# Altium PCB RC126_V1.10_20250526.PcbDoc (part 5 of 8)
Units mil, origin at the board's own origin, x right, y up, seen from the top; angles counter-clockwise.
Board outline 6299.62 x 3544.12 mil, 4 copper layers (Top, GND, Power, Bottom), stack 35.4 mil thick; 509 components, 417 nets, 1867 pads, 2150 vias.
Unrouted connection lines stored in the file: 1451.
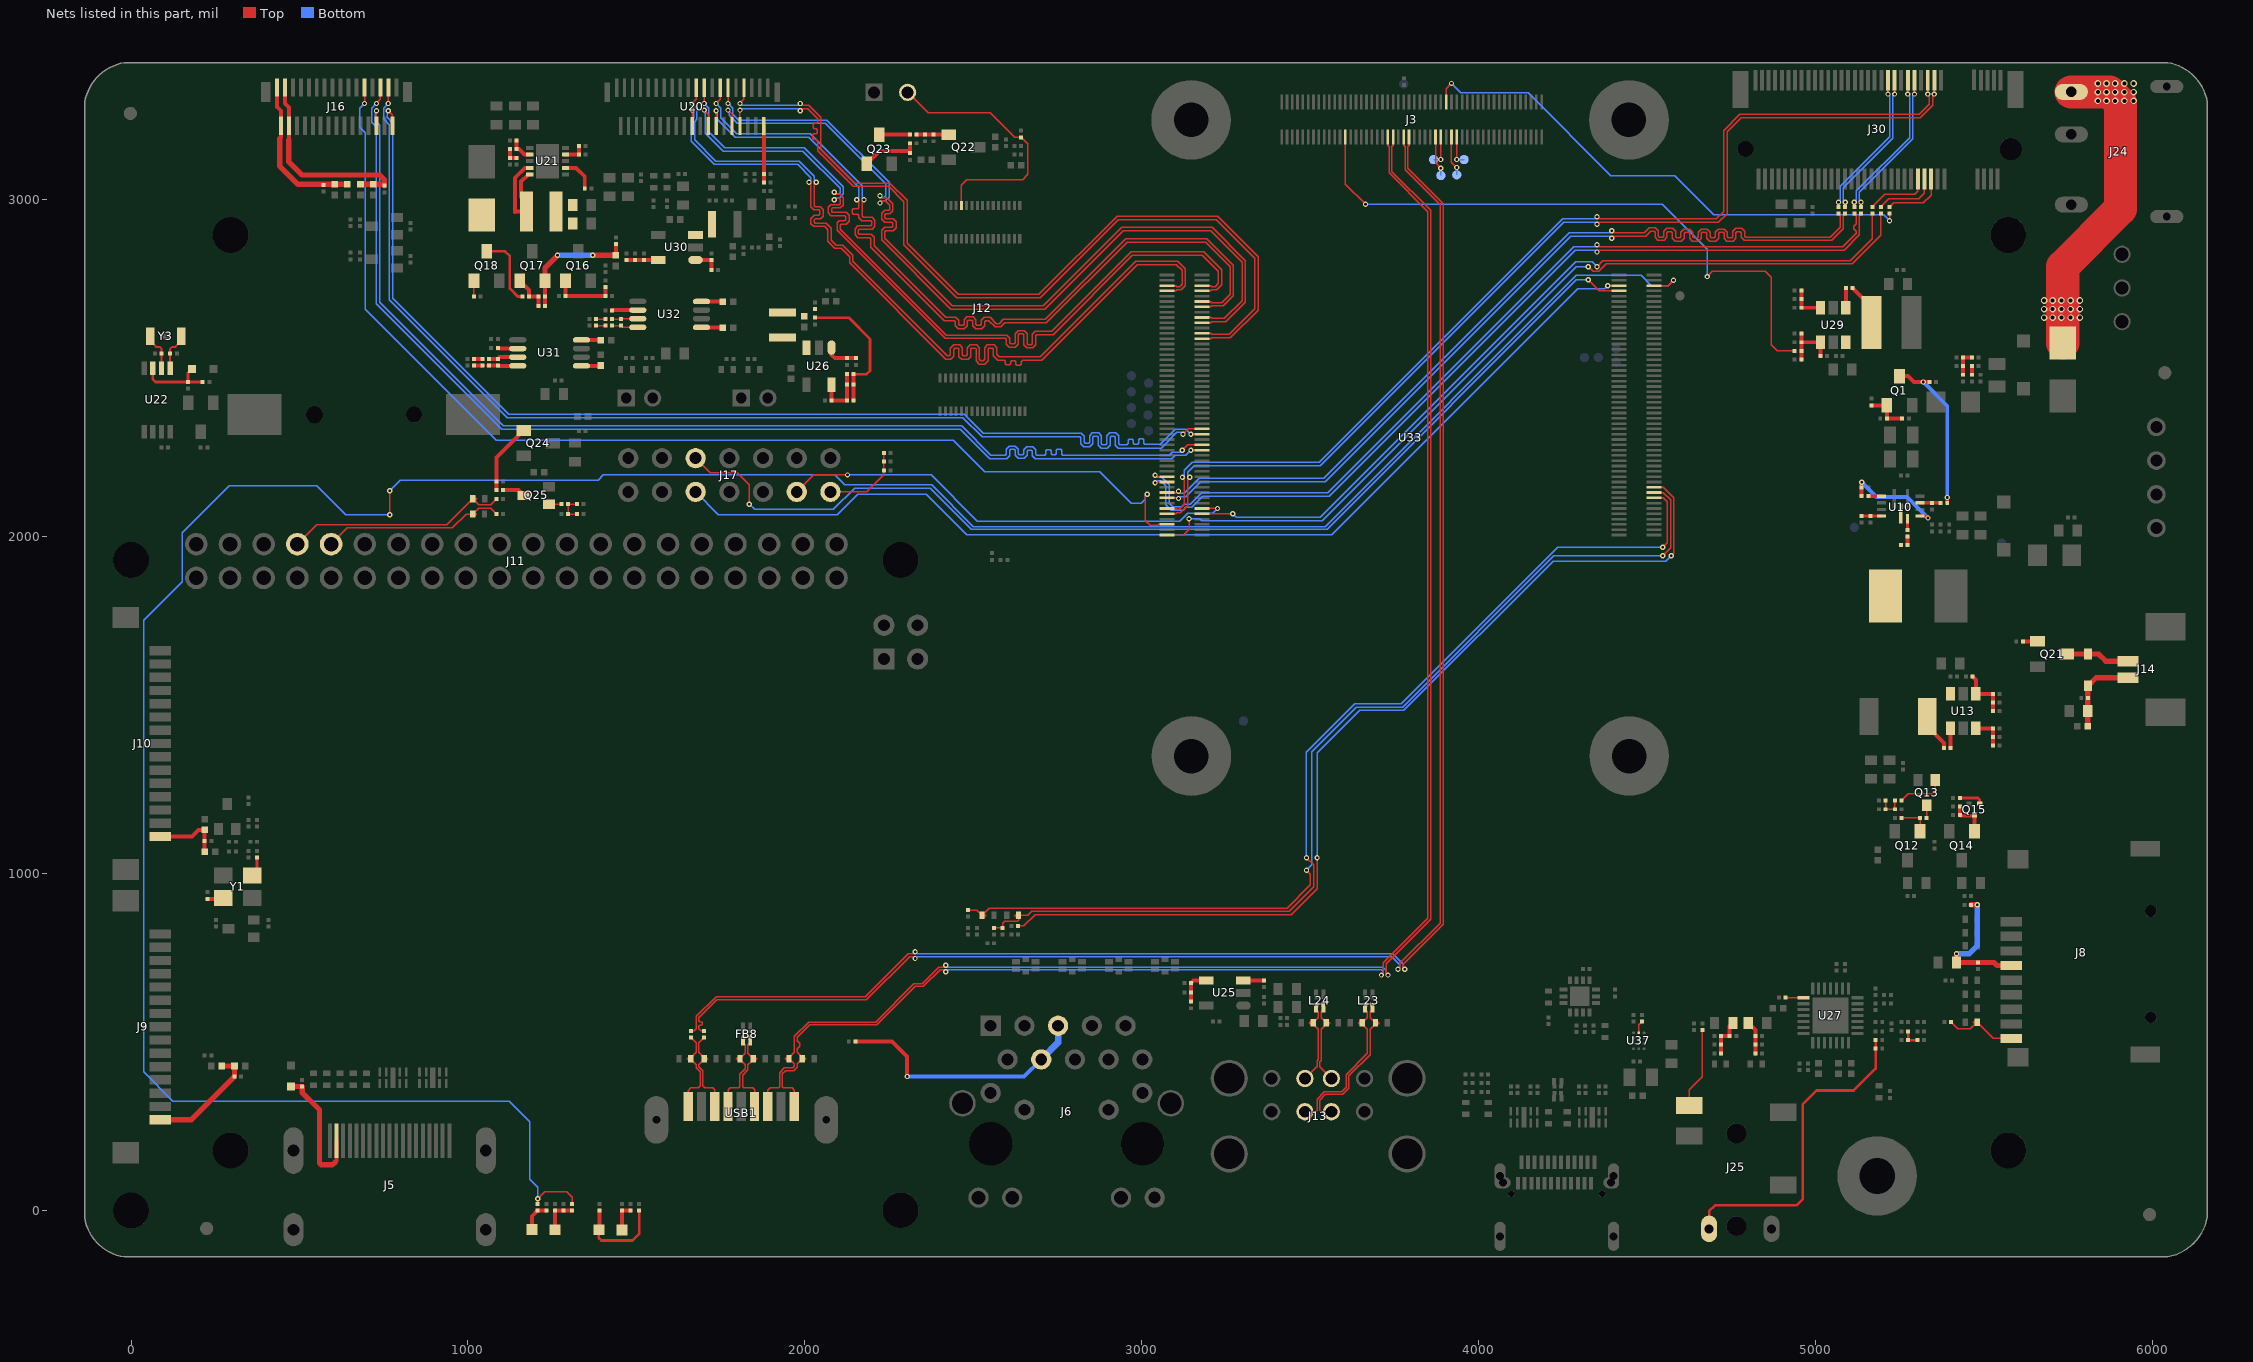
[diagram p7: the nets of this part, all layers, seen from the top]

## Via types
v1: diameter 15.75, hole 7.87, Top to Bottom, 2047 vias
v2: diameter 19.68, hole 11.81, Top to Bottom, 103 vias

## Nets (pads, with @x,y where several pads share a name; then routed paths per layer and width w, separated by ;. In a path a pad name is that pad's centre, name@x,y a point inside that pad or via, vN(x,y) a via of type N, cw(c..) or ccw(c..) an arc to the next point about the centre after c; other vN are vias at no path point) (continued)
MIPI_DPHY_CSI4_RX_CLKP: J16.9 U33.106 | length 3399.8
  Top w3.94: v1(692.91,3285.43) 692.91,3299.49 J16.9@692.91,3332.68 ; v1(3015.75,2125.98) 3009.84,2120.08 3009.84,2100.39 3009.84,2047.31 3023.89,2033.27 3046.26,2033.27 3049.21,2036.22 U33.106@3074.8,2036.22
  Bottom w3.94: v1(692.91,3285.43) 679.13,3271.65 679.13,3214.43 694.88,3198.68 694.88,2675.2 1083.66,2286.42 2439.96,2286.42 2533.46,2192.91 2874.02,2192.91 2968.5,2098.43 2998.03,2098.43 3009.84,2110.24 3009.84,2120.08 v1(3015.75,2125.98)
MIPI_DPHY_CSI4_RX_D0N: J16.5 U33.133 | length 3383.8
  Top w3.94: v1(728.35,3285.43) 740.16,3297.25 J16.5@740.16,3332.68 ; v1(3145.28,2256.69) U33.133@3178.74,2256.69
  Bottom w3.94: v1(728.35,3285.43) 714.57,3271.65 714.57,3230.32 728.35,3216.54 728.35,2690.81 1100.25,2318.9 1383.86,2318.9 2460.49,2318.9 2547.63,2231.76 2599.09,2231.76 2607.81,2240.47 2607.81,2255.91 2610.76,2258.86 2620.61,2258.86 2623.56,2255.91 2623.56,2241.99 2632.28,2233.27 2650.27,2233.27 2658.99,2241.99 2658.99,2253.94 2661.94,2256.89 2671.79,2256.89 2674.74,2253.94 2674.74,2240.02 2683.46,2231.3 3088.58,2231.3 3098.23,2240.94 3129.53,2240.94 v1(3145.28,2256.69)
MIPI_DPHY_CSI4_RX_D0P: J16.6 U33.135 | length 3386.7
  Top w3.94: J16.6@728.35,3219.5 728.35,3251.96 v1(728.35,3263.78) ; v1(3119.68,2256.69) 3135.43,2272.44 U33.135@3178.74,2272.44
  Bottom w3.94: v1(728.35,3263.78) 724.41,3259.84 724.41,3234.39 738.19,3220.61 738.19,2694.88 1104.33,2328.74 2330.51,2328.74 2464.57,2328.74 2551.71,2241.6 2595.02,2241.6 2597.97,2244.55 2597.97,2259.98 2606.69,2268.7 2624.68,2268.7 2633.4,2259.98 2633.4,2246.06 2636.35,2243.11 2646.2,2243.11 2649.15,2246.06 2649.15,2258.01 2657.87,2266.73 2675.86,2266.73 2684.58,2258.01 2684.58,2244.09 2686.78,2241.9 2711.39,2241.9 2714.57,2245.08 2714.57,2255.23 2717.52,2258.18 2727.36,2258.18 2730.32,2255.23 2730.32,2245.86 2733.27,2242.9 2743.11,2242.9 2746.06,2245.86 2746.06,2255.61 2749.02,2258.57 2758.86,2258.57 2761.81,2255.61 2761.81,2244.19 2764.86,2241.14 3080.71,2241.14 3090.35,2250.79 3113.78,2250.79 v1(3119.68,2256.69)
MIPI_DPHY_CSI4_RX_D1N: J16.2 U33.139 | length 3392.1
  Top w3.94: v1(763.78,3263.78) 775.59,3251.97 J16.2@775.59,3219.5 ; v1(3145.28,2303.94) U33.139@3178.74,2303.94
  Bottom w3.94: v1(763.78,3263.78) 759.84,3259.84 759.84,3244.23 776.57,3226.52 776.57,2706.83 1120.22,2363.19 2472.65,2363.19 2529.74,2306.1 2820.02,2306.1 2828.74,2297.38 2828.74,2279.53 2831.69,2276.57 2841.54,2276.57 2844.49,2279.53 2844.49,2299.35 2853.21,2308.07 2871.2,2308.07 2879.92,2299.35 2879.92,2275.59 2882.87,2272.64 2892.72,2272.64 2895.67,2275.59 2895.67,2299.35 2904.39,2308.07 2922.38,2308.07 2931.1,2299.35 2931.1,2275.59 2934.06,2272.64 2954.93,2272.64 2958.66,2276.37 2958.66,2285.98 2961.61,2288.94 2971.46,2288.94 2974.41,2285.98 2974.41,2276.37 2977.36,2273.42 2987.2,2273.42 2990.16,2276.37 2990.16,2287.51 2993.11,2290.47 3002.95,2290.47 3005.91,2287.51 3005.91,2276.57 3008.86,2273.62 3053.99,2273.62 3099.27,2318.9 3130.32,2318.9 v1(3145.28,2303.94)
MIPI_DPHY_CSI4_RX_D1P: J16.3 U33.141 | length 3383.6
  Top w3.94: v1(763.78,3285.43) 763.78,3299.49 J16.3@763.78,3332.68 ; v1(3121.65,2303.94) 3137.4,2319.69 U33.141@3178.74,2319.69
  Bottom w3.94: v1(763.78,3285.43) 750,3271.65 750,3240.16 766.73,3222.44 766.73,2702.76 1116.14,2353.35 2468.57,2353.35 2525.66,2296.26 2815.94,2296.26 2818.9,2293.31 2818.9,2275.45 2827.62,2266.73 2845.61,2266.73 2854.33,2275.45 2854.33,2295.28 2857.28,2298.23 2867.13,2298.23 2870.08,2295.28 2870.08,2271.51 2878.8,2262.8 2896.79,2262.8 2905.51,2271.51 2905.51,2295.28 2908.46,2298.23 2918.31,2298.23 2921.26,2295.28 2921.26,2271.51 2929.98,2262.8 3057.09,2262.8 3103.35,2309.06 3116.54,2309.06 v1(3121.65,2303.94)
MIPI_DPHY_DSI_TX_CLKN: U20.13 U33.187 | length 2466.5
  Top w3.94: v1(1736.22,3285.43) 1748.03,3297.24 U20.13@1748.03,3331.89 ; v1(2175.2,3000) 2169.29,2994.09 2169.29,2950.79 2172.24,2947.83 2198.96,2947.83 2207.68,2939.12 2207.68,2921.12 2198.96,2912.4 2161.42,2912.4 2158.46,2909.45 2158.46,2899.61 2161.42,2896.65 2196.99,2896.65 2205.71,2887.94 2205.71,2863.33 2417.99,2651.05 2447.52,2651.05 2456.24,2642.33 2456.24,2629.92 2459.19,2626.97 2469.03,2626.97 2471.98,2629.92 2471.98,2643.84 2480.7,2652.56 2498.7,2652.56 2507.42,2643.84 2507.42,2629.92 2510.37,2626.97 2520.21,2626.97 2523.17,2629.92 2523.17,2641.87 2531.88,2650.59 2549.88,2650.59 2568.35,2632.12 2576.54,2632.12 2589.11,2644.68 2712.6,2644.68 2951.77,2883.86 3192.91,2883.86 3271.65,2805.12 3271.65,2715.48 3241.01,2684.84 3207.68,2684.84 3204.72,2681.89 U33.187@3178.74,2681.89
  Bottom w3.94: v1(1736.22,3285.43) 1750,3271.65 1750,3242.27 1797.38,3194.88 2015.89,3194.88 2169.29,3041.48 2169.29,3005.91 v1(2175.2,3000)
MIPI_DPHY_DSI_TX_CLKP: U20.14 U33.189 | length 2450.3
  Top w3.94: U20.14@1736.22,3218.71 v1(1736.22,3263.78) ; v1(2153.54,3000) 2159.45,2994.09 2159.45,2975.39 2156.5,2972.44 2142.89,2972.44 2139.94,2969.49 2139.94,2959.65 2142.89,2956.69 2156.28,2956.69 2159.45,2953.52 2159.45,2946.71 2168.17,2937.99 2194.88,2937.99 2197.83,2935.04 2197.83,2925.2 2194.88,2922.24 2157.34,2922.24 2148.62,2913.53 2148.62,2895.53 2157.34,2886.81 2192.91,2886.81 2195.87,2883.86 2195.87,2859.25 2413.91,2641.21 2443.44,2641.21 2446.39,2638.25 2446.39,2625.84 2455.11,2617.13 2473.11,2617.13 2481.83,2625.84 2481.83,2639.76 2484.78,2642.72 2494.62,2642.72 2497.57,2639.76 2497.57,2625.84 2506.29,2617.13 2524.29,2617.13 2533.01,2625.84 2533.01,2637.8 2535.96,2640.75 2545.8,2640.75 2564.5,2622.05 2580.39,2622.05 2593.19,2634.84 2716.68,2634.84 2955.85,2874.02 3188.84,2874.02 3261.81,2801.04 3261.81,2719.56 3236.94,2694.68 3207.68,2694.68 3204.72,2697.64 U33.189@3178.74,2697.64
  Bottom w3.94: v1(1736.22,3263.78) 1740.16,3259.84 1740.16,3238.19 1793.31,3185.04 2011.81,3185.04 2159.45,3037.4 2159.45,3005.91 v1(2153.54,3000)
MIPI_DPHY_DSI_TX_D0N: U20.7 U33.175 | length 2464
  Top w3.94: v1(1807.09,3285.43) 1818.9,3297.24 U20.7@1818.9,3331.89 ; v1(1986.22,3285.43) 1992.13,3279.53 2011.81,3279.53 2047.24,3244.09 2047.24,3149.75 2147.78,3049.21 2252.11,3049.21 2303.15,2998.17 2303.15,2870.22 2454.86,2718.5 2693.9,2718.5 2926.18,2950.79 3224.41,2950.79 3344.49,2830.71 3344.49,2672.17 3262.67,2590.35 3207.68,2590.35 3204.72,2587.4 U33.175@3178.74,2587.4
  Bottom w3.94: v1(1807.09,3285.43) 1812.99,3279.53 1980.31,3279.53 v1(1986.22,3285.43)
MIPI_DPHY_DSI_TX_D0P: U20.8 U33.177 | length 2463.4
  Top w3.94: U20.8@1807.09,3218.71 v1(1807.09,3265.75) ; v1(1986.22,3263.78) 1992.13,3269.69 2007.73,3269.69 2037.4,3240.02 2037.4,3229.33 2034.45,3226.38 2027.25,3226.38 2024.3,3223.43 2024.3,3213.58 2027.25,3210.63 2033.37,3210.63 2036.32,3207.68 2036.32,3197.83 2033.37,3194.88 2026.16,3194.88 2023.2,3191.93 2023.2,3182.09 2026.16,3179.13 2031.92,3179.13 2037.4,3173.65 2037.4,3145.67 2143.7,3039.37 2248.03,3039.37 2293.31,2994.09 2293.31,2866.14 2450.79,2708.66 2697.97,2708.66 2930.26,2940.94 3220.33,2940.94 3334.65,2826.63 3334.65,2676.25 3258.59,2600.2 3207.68,2600.2 3204.72,2603.15 U33.177@3178.74,2603.15
  Bottom w3.94: v1(1807.09,3265.75) 1811.02,3269.69 1980.31,3269.69 v1(1986.22,3263.78)
MIPI_DPHY_DSI_TX_D1N: U20.10 U33.181 | length 2463.9
  Top w3.94: v1(1771.65,3265.75) 1783.46,3253.94 U20.10@1783.46,3218.71 ; v1(2222.44,3011.81) 2228.35,3005.91 2242.13,3005.91 2260.83,2987.2 2260.83,2967.38 2252.11,2958.66 2240.16,2958.66 2237.2,2955.71 2237.2,2945.87 2240.16,2942.91 2261.95,2942.91 2270.67,2934.2 2270.67,2916.2 2261.95,2907.48 2240.16,2907.48 2237.2,2904.53 2237.2,2884.98 2437.15,2685.04 2707.54,2685.04 2939.82,2917.32 3208.66,2917.32 3307.09,2818.9 3307.09,2695.8 3248.89,2637.6 3207.68,2637.6 3204.72,2634.65 U33.181@3178.74,2634.65
  Bottom w3.94: v1(1771.65,3265.75) 1770.74,3264.83 1775.59,3259.98 1775.59,3250 1799.21,3226.38 2060.88,3226.38 2240.16,3047.1 2240.16,3011.81 2234.25,3005.91 2228.35,3005.91 v1(2222.44,3011.81)
MIPI_DPHY_DSI_TX_D1P: U20.11 U33.183 | length 2465.1
  Top w3.94: v1(1771.65,3285.43) U20.11@1771.65,3331.89 ; v1(2222.44,2990.16) 2228.35,2996.06 2238.05,2996.06 2250.98,2983.13 2250.98,2971.46 2248.03,2968.5 2236.08,2968.5 2227.36,2959.79 2227.36,2941.79 2236.08,2933.07 2257.87,2933.07 2260.83,2930.12 2260.83,2920.28 2257.87,2917.32 2236.08,2917.32 2227.36,2908.6 2227.36,2904.53 2227.36,2880.91 2433.07,2675.2 2711.61,2675.2 2943.9,2907.48 3204.58,2907.48 3297.24,2814.82 3297.24,2699.87 3244.81,2647.44 3207.68,2647.44 3204.72,2650.39 U33.183@3178.74,2650.39
  Bottom w3.94: v1(1771.65,3285.43) 1785.43,3271.65 1785.43,3254.08 1803.29,3236.22 2064.96,3236.22 2250,3051.18 2250,3007.73 2238.33,2996.06 2228.35,2996.06 v1(2222.44,2990.16)
MIPI_DPHY_DSI_TX_D2N: U20.16 U33.193 | length 2455.7
  Top w3.94: v1(1700.79,3265.75) 1712.6,3253.94 U20.16@1712.6,3218.71 ; v1(2086.61,3021.65) 2087.6,3022.64 2094.49,3015.75 2104.33,3015.75 2114.17,3005.91 2114.17,2984.04 2105.4,2975.27 2081.57,2975.27 2078.74,2972.44 2078.74,2964.57 2080.71,2962.6 2122.19,2962.6 2130.91,2953.88 2130.91,2935.88 2122.19,2927.17 2108.27,2927.17 2105.31,2924.21 2105.31,2912.54 2419.96,2597.9 2599.09,2597.9 2607.81,2589.18 2607.81,2574.8 2610.76,2571.85 2620.61,2571.85 2623.56,2574.8 2623.56,2602.5 2632.28,2611.22 2650.27,2611.22 2658.99,2602.5 2658.99,2572.83 2661.94,2569.88 2671.79,2569.88 2674.74,2572.83 2674.74,2600.53 2683.46,2609.25 2732.21,2609.25 2967.84,2844.88 3182.68,2844.88 3236.22,2791.34 3236.22,2747.05 3221.26,2732.09 3207.68,2732.09 3204.72,2729.13 U33.193@3178.74,2729.13
  Bottom w3.94: v1(1700.79,3265.75) 1699.87,3264.83 1704.72,3259.98 1704.72,3196.85 1757.87,3143.7 1994.09,3143.7 2104.33,3033.46 2104.33,3021.17 2098.91,3015.75 2092.52,3015.75 v1(2086.61,3021.65)
MIPI_DPHY_DSI_TX_D2P: U20.17 U33.195 | length 2458.1
  Top w3.94: v1(1700.79,3285.43) U20.17@1700.79,3331.89 ; v1(2086.61,3000) 2092.52,3005.91 2100.25,3005.91 2104.33,3001.83 2104.33,2988.12 2101.45,2985.24 2077.13,2985.24 2068.9,2977 2068.9,2960.49 2076.63,2952.76 2118.11,2952.76 2121.06,2949.8 2121.06,2939.96 2118.11,2937.01 2101.38,2937.01 2095.47,2931.1 2095.47,2908.46 2415.88,2588.06 2595.02,2588.06 2597.97,2585.1 2597.97,2570.73 2606.69,2562.01 2624.68,2562.01 2633.4,2570.73 2633.4,2598.43 2636.35,2601.38 2646.2,2601.38 2649.15,2598.43 2649.15,2568.76 2657.87,2560.04 2675.86,2560.04 2684.58,2568.76 2684.58,2596.46 2687.53,2599.41 2736.29,2599.41 2971.91,2835.03 3178.61,2835.03 3226.38,2787.26 3226.38,2751.12 3217.18,2741.93 3207.68,2741.93 3204.72,2744.88 U33.195@3178.74,2744.88
  Bottom w3.94: v1(1700.79,3285.43) 1714.57,3271.65 1714.57,3200.93 1761.95,3153.54 1998.17,3153.54 2114.17,3037.54 2114.17,3017.09 2102.99,3005.91 2092.52,3005.91 v1(2086.61,3000)
MIPI_DPHY_DSI_TX_D3N: U20.19 U33.194 | length 2468.2
  Top w3.94: v1(1665.35,3285.43) 1677.17,3297.24 U20.19@1677.17,3331.89 ; v1(2033.46,3051.18) 2027.56,3045.28 2027.56,2982.28 2030.51,2979.33 2045.42,2979.33 2054.13,2970.61 2054.13,2950.79 2047.24,2943.9 2031.74,2943.9 2027.56,2939.71 2027.56,2933.07 2030.51,2930.12 2063.06,2930.12 2077.76,2915.42 2077.76,2879.99 2092.59,2865.16 2112.27,2865.16 2142.16,2835.27 2142.16,2816.57 2422.31,2536.42 2428.15,2536.42 2431.1,2539.37 2431.1,2559.19 2440.81,2568.9 2458.8,2568.9 2466.54,2561.16 2466.54,2539.37 2469.49,2536.42 2479.33,2536.42 2482.28,2539.37 2482.28,2561.16 2490.02,2568.9 2509.98,2568.9 2517.72,2561.16 2517.72,2525.59 2521.65,2521.65 2529.53,2521.65 2533.46,2525.59 2533.46,2561.16 2541.2,2568.9 2561.16,2568.9 2568.9,2561.16 2568.9,2541.34 2576.77,2533.46 2697.83,2533.46 2981.3,2816.93 3106.37,2816.93 3128.94,2794.36 3128.94,2744.09 3116.93,2732.09 3103.35,2732.09 3100.39,2729.13 U33.194@3074.8,2729.13
  Bottom w3.94: v1(1665.35,3285.43) 1679.13,3271.65 1679.13,3238.19 1672.24,3231.3 1672.24,3177.31 1735.38,3114.17 1982.28,3114.17 2027.56,3068.9 2027.56,3057.09 v1(2033.46,3051.18)
MIPI_DPHY_DSI_TX_D3P: U20.20 U33.196 | length 2466.7
  Top w3.94: U20.20@1665.35,3218.71 v1(1665.35,3265.75) ; v1(2011.81,3051.18) 2017.72,3045.28 2017.72,2978.21 2026.43,2969.49 2041.34,2969.49 2044.29,2966.54 2044.29,2956.69 2041.34,2953.74 2027.56,2953.74 2017.72,2943.9 2017.72,2928.99 2026.44,2920.28 2058.99,2920.28 2067.91,2911.35 2067.91,2875.91 2088.51,2855.32 2108.2,2855.32 2132.32,2831.2 2132.32,2812.49 2418.23,2526.58 2432.23,2526.58 2440.94,2535.3 2440.94,2555.12 2444.88,2559.06 2454.72,2559.06 2456.69,2557.09 2456.69,2533.46 2464.57,2525.59 2484.25,2525.59 2492.13,2533.46 2492.13,2557.09 2494.09,2559.06 2505.91,2559.06 2507.87,2557.09 2507.87,2521.51 2517.58,2511.81 2533.6,2511.81 2543.31,2521.51 2543.31,2557.09 2545.28,2559.06 2557.09,2559.06 2559.06,2557.09 2559.06,2537.26 2572.69,2523.62 2591.54,2523.62 2594.49,2520.67 2594.49,2513.03 2597.44,2510.07 2607.28,2510.07 2610.24,2513.03 2610.24,2519.59 2613.19,2522.55 2623.03,2522.55 2625.98,2519.59 2625.98,2511.12 2628.94,2508.17 2638.78,2508.17 2641.73,2511.12 2641.73,2518.9 2646.45,2523.62 2701.91,2523.62 2985.38,2807.09 3102.29,2807.09 3119.09,2790.28 3119.09,2748.17 3112.85,2741.93 3103.35,2741.93 3100.39,2744.88 U33.196@3074.8,2744.88
  Bottom w3.94: v1(1665.35,3265.75) 1669.29,3261.81 1669.29,3242.27 1662.4,3235.38 1662.4,3173.23 1731.3,3104.33 1978.21,3104.33 2017.72,3064.82 2017.72,3057.09 v1(2011.81,3051.18)
N16483578: C284.2 R334.1 | length 25.6
  Top w11.81: C284.2@1017.72,2527.56 R334.1@1043.31,2527.56
N16483700: C289.2 R335.1 | length 25.6
  Top w11.81: C289.2@1017.72,2507.87 R335.1@1043.31,2507.87
N16485789: C291.2 R336.1 | length 27.6
  Top w3.94: C291.2@1379.92,2645.67 R336.1@1407.48,2645.67
N16485911: C296.2 R337.1 | length 27.6
  Top w3.94: C296.2@1379.92,2625.98 R337.1@1407.48,2625.98
N17781029: LED2.1 R219.2 R221.2 | length 88.8
  Top w11.81: LED2.1@1189.82,-56.24 1189.82,-16.87 R221.2@1206.69,0 R219.2@1232.28,0
N17781033: LED3.1 R224.2 R227.1 | length 281.9
  Top w8: LED3.1@1388.64,-57.43 1387.8,-58.27 1387.8,-80.71 1395.67,-88.58 1488.19,-88.58 1507.87,-68.9 R227.1@1507.87,0
  Top w11.81: LED3.1@1388.64,-57.43 1389.76,-56.3 R224.2@1389.76,0
N17781361: LED2.2 R216.1 R217.1 R222.1 | length 107.7
  Top w11.81: LED2.2@1258.21,-56.35 1258.21,-0.34 R216.1@1257.87,0 R217.1@1283.46,0 R222.1@1309.06,0
N17782008: LED3.2 R225.1 R226.1 | length 83.3
  Top w11.81: LED3.2@1457.03,-57.54 1456.69,-57.2 R225.1@1456.69,0 R226.1@1482.28,0
N17782924: J17.13 R218.1 R220.1 R223.1 | length 244.5
  Top w3.94: J17.13@2075.59,2132.68 2183.86,2132.68 2234.25,2183.07 R218.1@2234.25,2196.85 R223.1@2234.25,2222.44 R220.1@2234.25,2248.03
N17878168: C278.2 C279.1 FB17.1 R317.1 | length 99.5
  Top w11.81: C278.2@4799.21,557.09 4820.87,535.43 R317.1@4820.87,517.72 C279.1@4820.87,492.13 FB17.1@4820.87,466.54
N17943889: R268.2 Y1.3 | length 66.9
  Top w7.87: Y1.3@360.24,994.09 374.02,994.09 R268.2@374.02,1047.24
N17943950: R264.1 Y1.1 | length 48.1
  Top w11.81: R264.1@226.38,925.2 257.87,925.2 259.85,927.17 Y1.1@273.62,927.17
N18372552: C192.1 C193.1 FB1.1 J9.1 | length 342.4
  Top w15.75: J9.1@86.61,269.7 179.14,269.7 C193.1@307.09,397.64 C192.1@307.09,429.13 FB1.1@269.69,429.13
N18373067: C190.1 C191.1 FB3.1 J10.1 | length 205
  Top w11.81: J10.1@86.61,1110.25 181.11,1110.25 200.79,1129.92 C190.1@218.5,1129.92 C191.1@218.5,1096.46 FB3.1@218.5,1064.96
N18669719: C277.1 R291.2 R304.1 | length 53.1
  Top w7.87: R291.2@5273.62,531.5 R304.1@5273.62,505.91 C277.1@5301.18,505.91
N19430296: D18.2 J8.9 R228.2 | length 214.5
  Top w3.94: R228.2@5401.57,559.06 5421.26,539.37 5458.66,539.37 D18.2@5478.35,559.06 5526.77,510.63 J8.9@5579.7,510.63
N19463865: J30.52 R296.1 | length 188.3
  Top w3.94: R296.1@5192.91,2978.35 5216.54,3001.97 5305.12,3001.97 5322.05,3018.9 J30.52@5322.05,3061.22
N19463875: C222.2 J30.49 | length 446
  Top w3.94: C222.2@5133.86,2978.35 v1(5133.86,2992.13) ; v1(5292.52,3313.19) J30.49@5292.52,3354.53
  Bottom w3.94: v1(5133.86,2992.13) 5128.94,2997.05 5128.94,3021.58 5287.6,3180.25 5287.6,3308.27 v1(5292.52,3313.19)
N19463877: C221.2 J30.47 | length 446
  Top w3.94: C221.2@5114.17,2978.35 v1(5114.17,2992.13) ; v1(5272.84,3313.19) J30.47@5272.83,3354.53
  Bottom w3.94: v1(5114.17,2992.13) 5119.09,2997.05 5119.09,3025.66 5277.76,3184.32 5277.76,3308.27 v1(5272.84,3313.19)
N19463923: J30.50 R295.1 | length 190.7
  Top w3.94: R295.1@5167.32,2978.35 5204.72,3015.75 5293.31,3015.75 5302.36,3024.8 J30.50@5302.36,3061.22
N19463941: C210.1 U29.1 | length 59.1
  Top w11.81: U29.1@5088.58,2679.13 C210.1@5088.58,2738.19
N19463943: C210.2 L21.1 U29.6 | length 126
  Top w11.81: C210.2@5108.27,2738.19 5165.35,2681.11 L21.1@5165.35,2635.83
N19463949: J30.54 R297.1 | length 185.8
  Top w3.94: R297.1@5218.5,2978.35 5230.32,2990.16 5318.9,2990.16 5341.73,3012.99 J30.54@5341.73,3061.22
N19463955: C217.2 R285.2 R290.1 U29.3 | length 108.3
  Top w11.81: R285.2@4956.69,2730.32 C217.2@4956.69,2704.72 R290.1@4956.69,2679.13 U29.3@5013.78,2679.13
N19463973: C220.1 R7.2 R278.1 R288.2 R298.2 U29.4 | length 178.1
  Top w11.81: R288.2@4956.69,2525.59 R7.2@4956.69,2551.18 R298.2@4956.69,2574.8 ; C220.1@4956.69,2602.36 R298.2@4956.69,2574.8 ; R278.1@5013.78,2535.43 U29.4@5013.78,2576.77 5013.78,2576.09 5013.1,2576.77 R298.2@4956.69,2576.77 R298.2@4956.69,2574.8
N19471161: J30.41 R293.2 | length 441.1
  Top w3.94: R293.2@5066.93,2978.35 v1(5066.93,2992.13) ; v1(5213.78,3313.19) J30.41@5213.78,3354.53
  Bottom w3.94: v1(5066.93,2992.13) 5071.85,2997.05 5071.85,3039.44 5218.7,3186.29 5218.7,3308.27 v1(5213.78,3313.19)
N19471204: J30.43 R294.2 | length 441.1
  Top w3.94: R294.2@5086.61,2978.35 v1(5086.61,2992.13) ; v1(5233.46,3313.19) J30.43@5233.46,3354.53
  Bottom w3.94: v1(5086.61,2992.13) 5081.69,2997.05 5081.69,3035.36 5228.54,3182.21 5228.54,3308.27 v1(5233.46,3313.19)
N19591793: C181.1 Q17.2 R254.2 R255.2 R257.1 | length 371.8
  Top w11.81: R257.1@1228.35,2685.04 C181.1@1228.35,2712.6 Q17.2@1228.34,2759.84 ; R254.2@1438.98,2834.65 R255.2@1438.98,2868.11
  Top w15.75: Q17.2@1228.34,2759.84 1228.34,2797.24 v1(1265.75,2834.65) ; v1(1370.08,2834.65) R254.2@1438.98,2834.65
  Bottom w15.75: v1(1265.75,2834.65) v1(1370.08,2834.65)
N19591801: C181.2 Q17.1 R257.2 R261.1 | length 113.8
  Top w11.81: Q17.1@1153.54,2759.84 1181.1,2732.28 R261.1@1181.1,2712.6 C181.2@1208.66,2712.6 R257.2@1208.66,2685.04
N19591813: Q18.3 R261.2 | length 218.3
  Top w7.87: Q18.3@1055.12,2846.46 1110.24,2846.46 1124.02,2832.68 1124.02,2736.22 1147.64,2712.6 R261.2@1161.42,2712.6
N19591825: Q18.1 R262.2 | length 47.2
  Top w3.94: R262.2@1017.72,2712.6 Q18.1@1017.72,2759.84
N19591849: C174.1 C176.1 FB2.2 L20.1 U21.7 | length 103.1
  Top w11.81: U21.7@1289.37,3094.49 1320.87,3094.49 1346.46,3068.9 C174.1@1346.46,3033.46
N19591855: D24.1 L20.2 U21.4 U21.5 | length 322.5
  Top w11.81: U21.5@1183.46,3074.8 1179.13,3074.8 1157.48,3053.15 1157.48,3007.87 1173.11,2992.25 L20.2@1173.11,2964.57 1141.73,2964.57 1139.76,2962.6 1139.76,3064.96 1169.29,3094.49 U21.4@1183.46,3094.49
N19591857: R240.1 R249.2 U21.2 | length 71.9
  Top w11.81: R240.1@1143.7,3175.2 R249.2@1143.7,3149.61 1151.57,3149.61 1167.32,3133.86 U21.2@1183.46,3133.86
N19591859: C180.2 R247.2 R249.1 | length 45.3
  Top w11.81: R249.1@1124.02,3149.61 R247.2@1124.02,3124.02 C180.2@1143.7,3124.02
N19591867: R236.2 R246.2 U21.9 | length 65
  Top w11.81: U21.9@1289.37,3133.86 R236.2@1328.74,3133.86 R246.2@1328.74,3159.45
N19592734: R229.2 R233.2 U20.2 | length 167.5
  Top w11.81: R233.2@1877.95,3051.18 R229.2@1877.95,3076.77 U20.2@1877.95,3218.71
N19592784: Q16.1 R234.2 R235.1 R243.2 | length 189
  Top w11.81: Q16.1@1289.37,2759.84 R243.2@1289.37,2714.57 R234.2@1407.48,2714.57 R235.1@1407.48,2740.16
N23443315: C275.2 C280.1 FB16.1 R286.2 R316.1 | length 120.2
  Top w11.81: FB16.1@4718.5,466.54 R316.1@4718.5,492.13 R286.2@4718.5,517.72 C280.1@4744.09,517.72 4744.09,547.24 C275.2@4753.94,557.09
N31344489: FB23.1 U31.8 | length 57.5
  Top w11.81: U31.8@1336.61,2583.67 1392.71,2583.67 FB23.1@1393.7,2582.68
N31344544: C283.2 U31.2 | length 59.5
  Top w11.81: C283.2@1088.58,2559.06 1089.56,2558.07 U31.2@1147.64,2558.07
N31344597: C286.1 R334.2 U31.3 | length 86.7
  Top w11.81: R334.2@1062.99,2527.56 C286.1@1088.58,2527.56 1093.5,2532.48 U31.3@1147.64,2532.48
N31344662: C286.2 R335.2 U31.4 | length 92.9
  Top w11.81: R335.2@1062.99,2507.87 1059.06,2507.87 C286.2@1088.58,2507.87 1089.57,2506.89 U31.4@1147.64,2506.89
N31344668: FB24.1 U31.5 | length 57.5
  Top w11.81: U31.5@1336.61,2506.89 1392.71,2506.89 FB24.1@1393.7,2507.87
N31367008: C293.1 R336.2 U32.3 | length 77.2
  Top w3.94: R336.2@1427.17,2645.67 C293.1@1454.72,2645.67 1455.71,2646.65 U32.3@1503.94,2646.65
N31367020: C293.2 R337.2 U32.4 | length 78.8
  Top w3.94: R337.2@1427.17,2625.98 C293.2@1454.72,2625.98 1459.65,2621.06 U32.4@1503.94,2621.06
N31367085: FB25.1 U32.8 | length 63.4
  Top w11.81: U32.8@1692.91,2697.84 1754.92,2697.84 FB25.1@1755.91,2696.85
N31367111: C290.2 U32.2 | length 77.2
  Top w11.81: C290.2@1427.17,2671.26 1428.15,2672.25 U32.2@1503.94,2672.25
N31367151: FB26.1 U32.5 | length 63.4
  Top w11.81: U32.5@1692.91,2621.06 1754.93,2621.06 FB26.1@1755.91,2620.08
N34109734: C167.1 C168.1 J8.4 R31.2 | length 402.3
  Top w15.75: v1(5417.32,761.81) C167.1@5417.32,736.22 C168.1@5480.32,736.22 5528.35,736.22 5537.4,727.17 J8.4@5579.7,727.17 ; R31.2@5460.63,907.48 v1(5478.35,907.48)
  Bottom w15.75: v1(5417.32,761.81) 5454.72,761.81 5478.35,785.43 v1(5478.35,907.48)
N37314098: L22.1 U26.3
N37314100: C201.1 C203.1 C206.1 L22.2 R284.1 R287.1 R289.1 | length 416
  Top w7.87: C206.1@2029.53,2649.61 2129.92,2649.61 2192.91,2586.61 2192.91,2492.13 2183.07,2482.28 R289.1@2143.7,2482.28
  Top w11.81: R287.1@2143.7,2403.54 C201.1@2143.7,2450.79 R289.1@2143.7,2482.28
N37314140: C201.2 R287.2 R289.2 R318.1 U26.5 | length 171.3
  Top w11.81: U26.5@2078.74,2450.79 R318.1@2078.74,2403.54 R287.2@2124.02,2403.54 C201.2@2124.02,2450.79 R289.2@2124.02,2482.28
N37314178: L29.1 U30.3
N37314204: R331.2 R332.1 U30.1 | length 76.8
  Top w11.81: U30.1@1675.2,2820.87 R332.1@1722.44,2820.87 R331.2@1722.44,2791.34
N37314206: C242.2 R329.2 R330.1 U30.5 | length 96.5
  Top w3.94: R330.1@1519.68,2820.87 R330.1@1521.65,2820.87
  Top w11.81: R329.2@1470.47,2820.87 C242.2@1496.06,2820.87 1519.68,2820.87 U30.5@1564.96,2820.87
N37314307: C228.2 Q22.1 R321.2 R322.1 | length 96.5
  Top w11.81: R322.1@2330.71,3192.91 C228.2@2356.3,3192.91 R321.2@2381.89,3192.91 2396.65,3192.91 Q22.1@2427.16,3192.91
N37314321: Q23.3 R322.2 | length 90.6
  Top w11.81: Q23.3@2220.47,3192.92 2270.67,3192.92 R322.2@2311.02,3192.91
N37314323: C232.1 Q23.1 R323.2 | length 178.9
  Top w11.81: Q23.1@2183.07,3106.3 2220.48,3143.7 2311.02,3143.7 C232.1@2311.02,3137.8 R323.2@2311.02,3167.32
N38149696: C175.1 D8.2 J5.18 | length 399.4
  Top w11.81: 604.33,142.05 609.92,147.64 J5.18@609.92,207.82
  Top w15.75: D8.2@474.41,368.11 C175.1@507.87,368.11 507.87,350.39 559.06,299.21 559.06,141.73 564.96,135.83 598.11,135.83 604.33,142.05
N38162604: C150.1 R181.2 U10.6 | length 59.1
  Top w9.84: R181.2@5135.83,2061.02 C150.1@5161.42,2061.02 U10.6@5194.88,2061.02
N38162840: C163.1 R185.2 R202.1 R204.2 U13.4 | length 157.6
  Top w11.81: R185.2@5464.57,1584.65 5474.41,1574.8 U13.4@5474.41,1533.46 C163.1@5525.59,1533.46 R202.1@5525.59,1507.87 R204.2@5525.59,1482.28
N38162882: C152.2 L15.1 U13.6 | length 114.9
  Top w11.81: L15.1@5330.71,1466.54 5336.61,1460.63 5336.61,1431.1 5379.92,1387.8 C152.2@5379.92,1372.05
N38162884: C152.1 U13.1 | length 59.1
  Top w11.81: C152.1@5399.61,1372.05 U13.1@5399.61,1431.1
N38162900: C160.2 R187.2 R205.1 U13.3 | length 102.4
  Top w11.81: U13.3@5474.41,1431.1 R205.1@5525.59,1431.1 R187.2@5525.59,1405.51 C160.2@5525.59,1379.92
N38162991: D4.1 J24.1 | length 942.6
  Top w98.43: D4.1@5732.28,2574.8 5732.28,2801.18 5903.54,2972.44 5903.54,3287.4 5871.26,3319.69 J24.1@5757.87,3319.69
  other v2: 5677.17,2649.61 5702.76,2649.61 5728.35,2649.61 5755.91,2649.61 5783.46,2649.61 5677.17,2675.2 5702.76,2675.2 5728.35,2675.2 5755.91,2675.2 5783.46,2675.2 5677.17,2700.79 5702.76,2700.79 5728.35,2700.79 5755.91,2700.79 5783.46,2700.79 5836.61,3293.31 5862.2,3293.31 5887.8,3293.31 5915.35,3293.31 5942.91,3293.31 5836.61,3318.9 5862.2,3318.9 5887.8,3318.9 5915.35,3318.9 5942.91,3318.9 5836.61,3344.49 5862.2,3344.49 5887.8,3344.49 5915.35,3344.49 5942.91,3344.49
N38163032: C155.2 R201.2 | length 25.6
  Top w11.81: C155.2@5462.6,2480.31 R201.2@5462.6,2505.91
N38163042: C148.1 R176.1 R178.2 R179.2 | length 76.8
  Top w11.81: R176.1@5437.01,2480.31 C148.1@5437.01,2505.91 R179.2@5437.01,2531.5 R178.2@5462.6,2531.5
N38163178: C151.1 R182.2 U10.9 | length 308.3
  Top w7.87: U10.9@5309.06,2061.02 5326.77,2061.02 v1(5332.68,2055.12)
  Top w11.81: R182.2@5135.83,2120.08 C151.1@5135.83,2145.67 v1(5135.83,2161.42)
  Bottom w11.81: v1(5135.83,2161.42) 5179.13,2118.11 5269.68,2118.11 v1(5332.68,2055.12)
N38163182: C77.2 L2.1 U10.7
N38163194: R115.1 U10.8 | length 33.5
  Top w9.84: R115.1@5271.65,2019.69 U10.8@5271.66,2053.15
N38163196: C77.1 R115.2 | length 25.6
  Top w11.81: C77.1@5271.65,1974.41 R115.2@5271.65,2000
N38163206: R175.1 R177.2 U10.11 | length 63
  Top w3.94: R177.2@5344.49,2100.39 R177.2@5346.45,2100.39
  Top w9.84: U10.11@5309.06,2100.39 5346.46,2100.39 R175.1@5370.08,2100.39
N38163220: R182.1 U10.3 | length 39.4
  Top w9.84: R182.1@5155.51,2120.08 U10.3@5194.88,2120.08
N38163995: Q12.1 R206.1 R208.1 | length 94.5
  Top w3.94: R206.1@5253.94,1165.35 R208.1@5309.06,1165.35 Q12.1@5309.05,1125.99
N38164007: R209.2 R210.1 R326.2 R327.2 | length 78.7
  Top w3.94: R326.2@5206.69,1216.54 R327.2@5206.69,1190.94 R210.1@5234.25,1190.94 R209.2@5234.25,1216.54
N38164009: Q13.1 R209.1 | length 144.1
  Top w3.94: R209.1@5253.94,1216.54 5273.62,1236.22 5344.49,1236.22 5354.33,1246.06 Q13.1@5354.33,1277.56
N38164029: Q13.3 R208.2 | length 37.4
  Top w3.94: R208.2@5328.74,1165.35 Q13.3@5328.74,1202.76
N38175041: C173.2 Q14.1 Q15.3 R213.1 | length 115.2
  Top w11.81: C173.2@5427.17,1198.82 R213.1@5427.17,1173.23 5428.74,1171.65 Q15.3@5470.37,1171.65 5470.47,1171.56 Q14.1@5470.47,1125.99
N38175045: Q15.1 R230.2 | length 71.3
  Top w7.87: R230.2@5427.17,1224.41 5480.32,1224.41 5486.22,1218.5 Q15.1@5486.22,1208.66
N38179051: C187.2 U22.1 Y3.1 | length 114.1
  Top w5.91: U22.1@116.14,2500 C187.2@116.14,2543.31 116.14,2557.09 122.05,2562.99 131.89,2562.99 147.64,2578.74 147.64,2592.52 Y3.1@149.61,2594.49
N38179153: C189.2 U22.2 Y3.2 | length 114.1
  Top w5.91: Y3.2@57.09,2594.49 59.06,2592.52 59.06,2578.74 74.8,2562.99 84.65,2562.99 90.55,2557.09 C189.2@90.55,2543.31 U22.2@90.55,2500
N38179175: D30.2 R16.2 R265.2 U22.3 | length 228.6
  Top w7.87: U22.3@64.96,2500 64.96,2466.54 72.83,2458.66 R16.2@169.29,2458.66 ; D30.2@181.1,2498.03 169.29,2486.22 R16.2@169.29,2458.66 ; R265.2@212.6,2458.66 R16.2@169.29,2458.66
N38183775: D3.1 J11.8 R273.1 | length 661.7
  Top w3.94: J11.8@493.7,1977.56 551.57,2035.43 937.01,2035.43 D3.1@1014.17,2112.6 1032.28,2094.49 1066.93,2094.49 R273.1@1084.65,2112.2
N38194639: D2.1 J11.10 R274.1 | length 542.6
  Top w3.94: J11.10@593.7,1977.56 641.73,2025.59 952.76,2025.59 994.09,2066.93 D2.1@1013.78,2066.93 1031.5,2084.65 1066.93,2084.65 R274.1@1084.65,2066.93
N38198421: D35.2 FB8.3 R283.1 USB1.3 | length 258.1
  Top w3.94: R283.1@1836.61,513.78 1836.61,499.01 FB8.3@1837.6,499.01 1830.71,492.12 1830.71,466.54 D35.2@1846.46,450.79 1839.97,441.35 1830.71,432.09 1830.71,417.32 1814.96,401.57 1814.96,367.13 1817.91,364.17 1844.49,364.17 1850.39,358.27 USB1.3@1850.39,308.66
N38198427: C204.2 D39.2 USB1.8 | length 256.7
  Top w3.94: C204.2@1700.79,513.78 1685.04,498.03 1685.04,494.09 1685.04,469.49 1694.31,460.22 D39.2@1700.79,450.79 1694.31,441.35 1685.04,432.09 1685.04,426.49 1696.85,414.68 1696.85,370.08 1702.76,364.17 1726.38,364.17 1732.28,358.27 USB1.8@1732.28,308.66
N38198429: C205.2 D37.2 USB1.9 | length 255.6
  Top w3.94: USB1.9@1653.54,308.66 1653.54,356.3 1661.42,364.17 1683.07,364.17 1688.98,370.08 1688.98,411.42 1677.17,423.23 1677.17,432.09 1667.9,441.35 D37.2@1661.42,450.79 1667.9,460.22 1677.17,469.49 1677.17,494.09 1677.17,498.03 C205.2@1661.42,513.78
N38198493: D38.2 FB8.4 R282.1 USB1.2 | length 257.5
  Top w3.94: USB1.2@1771.65,308.66 1771.65,358.27 1777.56,364.17 1804.13,364.17 1807.09,367.13 1807.09,404.84 1822.83,420.58 1822.83,432.09 1813.57,441.35 D38.2@1807.09,450.79 1822.83,466.54 1822.83,492.12 FB8.4@1815.94,499.01 1816.93,500 R282.1@1816.93,513.78
N38202668: R277.2 R279.1 R280.1 U25.4 | length 103.7
  Top w11.81: R277.2@3145.67,620.08 R280.1@3145.67,647.64 R279.1@3145.67,675.2 3153.54,683.07 U25.4@3190.95,683.07
N38213216: R354.1 U37.D2 | length 37.5
  Top w3.94: U37.D2@4474.41,527.56 4474.41,551.18 R354.1@4484.25,561.02
N38228022: C197.1 C200.1 D6.2 FB9.2 J14.2 | length 251.3
  Top w3.94: C197.1@5807.09,1519.69 C197.1@5807.09,1521.65
  Top w15.75: FB9.2@5807.09,1437.01 C200.1@5807.09,1482.28 5807.09,1519.69 D6.2@5807.09,1557.09 5831.1,1581.1 J14.2@5926.38,1581.1
N38228074: D6.1 J14.1 Q21.3 | length 191.1
  Top w15.75: Q21.3@5744.1,1651.57 D6.1@5807.09,1651.57 5838.98,1651.57 5860.24,1630.32 J14.1@5926.38,1630.32
N38228088: Q21.1 R14.2 | length 43.3
  Top w11.81: R14.2@5614.17,1688.98 Q21.1@5657.48,1688.97
N38240450: C231.1 C233.1 FB4.1 J16.28 J16.29 | length 624.2
  Top w3.94: C233.1@718.5,3045.28 C233.1@719.36,3045.28
  Top w11.02: 468.5,3177.17 J16.28@468.5,3219.5
  Top w11.81: J16.29@456.69,3332.68 456.69,3285.43 468.5,3273.62 J16.28@468.5,3219.5
  Top w15.75: 468.5,3177.17 468.5,3112.2 507.87,3072.83 738.19,3072.83 751.97,3059.06 C231.1@751.97,3041.34 751.97,3045.28 719.36,3045.28 FB4.1@681.1,3045.28
N38240452: C234.1 C235.1 FB5.1 J16.30 J16.31 | length 465.3
  Top w3.94: C235.1@569.42,3045.28 570.87,3043.83 C235.1@570.87,3043.31 ; C234.1@604.02,3045.28 C234.1@604.33,3045.28
  Top w11.02: 440.94,3181.1 444.88,3185.04 J16.30@444.88,3219.5
  Top w11.81: J16.31@433.07,3332.68 433.07,3275.59 444.88,3263.78 J16.30@444.88,3219.5
  Top w15.75: 440.94,3181.1 440.94,3100.39 496.06,3045.28 569.42,3045.28 604.02,3045.28 FB5.1@641.73,3045.28
N38245392: Q24.1 R344.1 R350.1 | length 210.6
  Top w11.81: R350.1@1084.65,2137.8 R344.1@1084.65,2163.39 1084.65,2234.25 Q24.1@1165.35,2314.96
N38245412: R356.2 R357.2 R358.2 R359.1 | length 80.7
  Top w3.94: R356.2@1322.83,2066.93 R359.1@1297.24,2066.93 R358.2@1297.24,2096.46 R357.2@1322.83,2096.46
N38245414: Q25.1 R358.1 | length 37.4
  Top w3.94: Q25.1@1240.16,2096.46 R358.1@1277.56,2096.46
N38245434: Q25.3 R350.2 | length 67.5
  Top w11.81: R350.2@1104.33,2137.8 1149.61,2137.8 Q25.3@1165.36,2122.05
N38274077: Q1.3 R1.2 R175.2 | length 483.5
  Top w11.81: Q1.3@5248.03,2476.38 5273.62,2476.38 5291.34,2458.66 v1(5318.9,2458.66) R1.2@5336.61,2458.66 ; R175.2@5389.76,2100.39 v1(5389.76,2116.14)
  Bottom w11.81: v1(5318.9,2458.66) 5389.76,2387.8 v1(5389.76,2116.14)
N38274095: Q1.1 R2.2 R5.1 R6.2 | length 134
  Top w11.81: R2.2@5165.35,2389.76 5207.76,2389.76 5210.63,2386.89 Q1.1@5210.63,2389.76 R6.2@5210.63,2350.39 R5.1@5255.91,2350.39
N38368976: J2.2 J12.46 R15.2 | length 781.6
  Top w3.94: J2.2@2304.72,3318.5 2365.35,3257.87 2549.21,3257.87 2622.05,3185.04 R15.2@2641.73,3185.04 2661.42,3165.35 2661.42,3074.8 2645.67,3059.06 2480.51,3059.06 2464.17,3042.72 J12.46@2464.17,2982.28
N38434760: D41.2 J13.2 L23.4 R299.2 | length 461
  Top w3.94: J13.2@3483.46,293.31 3515.75,293.31 3519.68,297.24 3519.68,330.71 3541.34,352.36 3592.52,352.36 3606.3,366.14 3606.3,403.21 3669.29,466.2 3669.29,538.39 3660.03,547.65 D41.2@3653.54,557.09 3669.29,572.83 3669.29,590.54 L23.4@3662.4,597.44 3663.39,597.44 R299.2@3663.39,612.2
N38434788: D42.2 J13.3 L23.3 R301.2 | length 458.8
  Top w3.94: J13.3@3562.2,293.31 3531.5,293.31 3527.56,297.24 3527.56,327.45 3544.6,344.49 3595.78,344.49 3614.17,362.88 3614.17,399.94 3677.17,462.94 3677.17,538.39 3686.43,547.65 D42.2@3692.91,557.09 3677.17,572.83 3677.17,590.54 L23.3@3684.06,597.44 3683.07,598.42 R301.2@3683.07,612.2
N38448541: R281.1 U25.3 | length 61
  Top w11.81: U25.3@3301.18,683.07 R281.1@3362.2,683.07
N38452344: D44.2 J13.6 L24.4 R300.2 | length 252.7
  Top w3.94: J13.6@3483.46,391.73 3519.68,427.95 3519.68,444.54 3523.62,448.48 3523.62,538.39 3514.36,547.65 D44.2@3507.87,557.09 3523.62,572.83 3523.62,590.54 L24.4@3516.73,597.44 3517.72,598.42 R300.2@3517.72,612.2
N38452372: D43.2 J13.7 L24.3 R302.2 | length 252.1
  Top w3.94: R302.2@3537.4,612.2 3537.4,598.42 L24.3@3538.39,597.44 3531.5,590.54 3531.5,572.83 D43.2@3547.24,557.09 3540.76,547.65 3531.5,538.39 3531.5,445.22 3527.56,441.28 3527.56,426.38 J13.7@3562.2,391.73
N38457128: C169.2 J6.4 J6.5 | length 771.1
  Top w11.81: C169.2@2149.61,501.97 2257.87,501.97 2303.15,456.69 v1(2303.15,397.64)
  Bottom w11.81: v1(2303.15,397.64) 2650.39,397.64 J6.4@2701.18,448.43
  Bottom w19.68: J6.4@2701.18,448.43 2751.18,498.43 J6.5@2751.18,548.43
N38490894: J25.2 R26.2 R27.2 | length 971.3
  Top w7.87: J25.2@4683.07,-54.33 4683.07,-1.97 4700.79,15.75 4942.91,15.75 4960.63,33.46 4960.63,314.96 5001.97,356.3 5112.2,356.3 5177.17,421.26 R27.2@5177.17,480.32 R26.2@5177.17,505.91
N38492034: J25.4 R19.2 | length 239.9
  Top w3.94: J25.4@4624.02,311.81 4624.02,358.27 4663.39,397.64 R19.2@4663.39,535.43
N38837471: R276.2 U27.8 | length 53.1
  Top w3.94: R276.2@4909.45,631.89 U27.8@4962.6,631.89
N39005536: R303.2 R315.1 U26.1 | length 98.6
  Top w11.81: U26.1@2078.74,2561.02 2078.74,2539.37 2088.58,2529.53 R315.1@2124.02,2529.53 R303.2@2151.57,2529.53
NPWR_LED: R221.1 R222.2 U33.95 | length 8310.7
  Top w3.94: v1(767.72,2064.96) v1(767.72,2135.83) ; R221.1@1206.69,19.69 v1@1206.69,34.6 ; v1(1206.69,35.43) v1@1206.69,34.6 ; R222.2@1309.06,19.69 1309.06,39.37 1293.31,55.12 1227.22,55.12 v1@1206.69,34.6 ; U33.95@4520.08,2744.88 4561.42,2744.88 v1(4577.17,2760.63)
  Bottom w3.94: v1(767.72,2064.96) 637.8,2064.96 551.18,2151.57 291.34,2151.57 151.57,2011.81 151.57,1866.14 37.4,1751.97 37.4,411.42 124.02,324.8 1122.05,324.8 1183.07,263.78 1183.07,92.52 1206.69,68.9 v1(1206.69,35.43) ; v1(767.72,2135.83) 799.21,2167.32 1385.83,2167.32 1401.57,2183.07 2088.58,2183.07 2118.11,2153.54 2375.98,2153.54 2500,2029.53 3543.31,2029.53 4289.37,2775.59 4481.1,2775.59 4511.81,2744.88 4561.42,2744.88 v1(4577.17,2760.63)
PCIE0_CLKREQN_M0: R296.2 U33.102 | length 2586.1
  Top w3.94: U33.102@3074.8,2004.72 3122.83,2004.72 3139.76,2021.65 v1(3139.76,2053.15) ; v1(4324.8,2801.18) 4338.58,2787.4 4356.3,2787.4 4377.95,2809.06 5108.27,2809.06 5192.91,2893.7 R296.2@5192.91,2958.66
  Bottom w3.94: v1(3139.76,2053.15) 3171.8,2053.15 3177.71,2047.24 3535.43,2047.24 4289.37,2801.18 v1(4324.8,2801.18)
PCIE0_PERSTN: R295.2 U33.109 | length 2421.7
  Top w3.94: U33.109@3178.74,2067.72 v1(3269.29,2067.72) ; v1(4350.39,2801.18) 4368.11,2818.9 5102.36,2818.9 5167.32,2883.86 R295.2@5167.32,2958.66
  Bottom w3.94: v1(3269.29,2067.72) 3279.92,2057.09 3529.53,2057.09 4287.4,2814.96 4336.61,2814.96 v1(4350.39,2801.18)
PCIE0_PWREN_H: J3.76 R7.1 | length 1856.2
  Top w3.94: J3.76@3603.55,3185.83 3603.55,3177.1 3603.54,3046.06 v1(3663.39,2986.22) ; v1(4677.17,2771.65) 4692.91,2787.4 4850.39,2787.4 4868.11,2769.69 4868.11,2568.9 4885.83,2551.18 R7.1@4937.01,2551.18
  Bottom w3.94: v1(3663.39,2986.22) 4543.31,2986.22 4677.17,2852.36 v1(4677.17,2771.65)
PCIE0_SOC_REFCLKN: J30.53 U33.112 | length 3043.9
  Top w3.94: U33.112@3074.8,2083.46 3100.39,2083.46 3103.35,2080.51 3110.1,2080.51 3125.98,2096.4 3125.98,2170.08 v1(3120.08,2175.98) ; v1(4350.39,2948.82) 4356.3,2942.91 4704.65,2942.91 4726.38,2964.64 4726.38,3204.79 4774.54,3252.95 5306.23,3252.95 5336.81,3283.53 5336.81,3308.27 v1(5331.89,3313.19) J30.53@5331.89,3354.53
  Bottom w3.94: v1(3120.08,2175.98) 3125.98,2181.89 3125.98,2196.85 3149.61,2220.47 3525.59,2220.47 4248.03,2942.91 4344.49,2942.91 v1(4350.39,2948.82)
PCIE0_SOC_REFCLKP: J30.55 U33.110 | length 3060.7
  Top w3.94: U33.110@3074.8,2067.72 3100.39,2067.72 3103.35,2070.67 3114.17,2070.67 3135.83,2092.32 3135.83,2170.08 v1(3141.73,2175.98) ; v1(4350.39,2927.17) 4356.3,2933.07 4710.7,2933.07 4736.22,2958.59 4736.22,3200.72 4778.61,3243.11 5310.31,3243.11 5346.65,3279.46 5346.65,3308.27 v1(5351.58,3313.19) J30.55@5351.57,3354.53
  Bottom w3.94: v1(3141.73,2175.98) 3135.83,2181.89 3135.83,2191.73 3154.72,2210.63 3529.67,2210.63 4252.11,2933.07 4344.49,2933.07 v1(4350.39,2927.17)
PCIE0_SOC_RXN: R293.1 U33.118 | length 2601.9
  Top w3.94: U33.118@3074.8,2130.71 3104.33,2130.71 v1(3108.27,2134.65) ; v1(4393.7,2907.48) 4393.7,2903.54 4395.67,2901.57 4491,2901.57 4505.77,2916.34 4523.76,2916.34 4532.48,2907.62 4532.48,2891.73 4535.43,2888.78 4545.28,2888.78 4548.23,2891.73 4548.23,2905.65 4556.95,2914.37 4574.94,2914.37 4583.66,2905.65 4583.66,2889.76 4586.61,2886.81 4596.46,2886.81 4599.41,2889.76 4599.41,2903.68 4608.13,2912.4 4626.12,2912.4 4634.84,2903.68 4634.84,2889.76 4637.8,2886.81 4647.64,2886.81 4650.59,2889.76 4650.59,2903.68 4659.31,2912.4 4677.31,2912.4 4686.02,2903.68 4686.02,2889.76 4688.98,2886.81 4698.82,2886.81 4701.77,2889.76 4701.77,2903.68 4710.49,2912.4 4728.49,2912.4 4737.2,2903.68 4737.2,2889.76 4740.16,2886.81 4750,2886.81 4752.95,2889.76 4752.95,2905.65 4761.67,2914.37 4779.67,2914.37 4788.39,2905.65 4788.39,2891.73 4791.34,2888.78 5043.24,2888.78 5071.85,2917.39 5071.85,2953.74 R293.1@5066.93,2958.66
  Bottom w3.94: v1(3108.27,2134.65) 3114.17,2128.74 3125.84,2128.74 3170.33,2173.23 3183.99,2173.23 3539.37,2173.23 4267.72,2901.57 4387.8,2901.57 v1(4393.7,2907.48)
PCIE0_SOC_RXP: R294.1 U33.116 | length 2617.4
  Top w3.94: U33.116@3074.8,2114.96 3106.3,2114.96 v1(3108.27,2112.99) ; v1(4393.7,2885.83) 4393.7,2889.76 4395.67,2891.73 4495.08,2891.73 4509.84,2906.5 4519.69,2906.5 4522.64,2903.54 4522.64,2887.66 4531.36,2878.94 4549.35,2878.94 4558.07,2887.66 4558.07,2901.57 4561.02,2904.53 4570.87,2904.53 4573.82,2901.57 4573.82,2885.69 4582.54,2876.97 4600.53,2876.97 4609.25,2885.69 4609.25,2899.61 4612.2,2902.56 4622.05,2902.56 4625,2899.61 4625,2885.69 4633.72,2876.97 4651.71,2876.97 4660.43,2885.69 4660.43,2899.61 4663.39,2902.56 4673.23,2902.56 4676.18,2899.61 4676.18,2885.69 4684.9,2876.97 4702.9,2876.97 4711.61,2885.69 4711.61,2899.61 4714.57,2902.56 4724.41,2902.56 4727.36,2899.61 4727.36,2885.69 4736.08,2876.97 4754.08,2876.97 4762.8,2885.69 4762.8,2901.57 4765.75,2904.53 4775.59,2904.53 4778.54,2901.57 4778.54,2887.66 4787.26,2878.94 5047.31,2878.94 5081.69,2913.32 5081.69,2953.74 R294.1@5086.61,2958.66
  Bottom w3.94: v1(3108.27,2112.99) 3114.17,2118.9 3129.92,2118.9 3174.41,2163.39 3543.45,2163.39 4271.79,2891.73 4387.8,2891.73 v1(4393.7,2885.83)
PCIE0_SOC_TXN: C221.1 U33.124 | length 2596.5
  Top w3.94: v1(3038.98,2181.89) 3042.91,2177.95 U33.124@3074.8,2177.95 ; v1(4350.39,2866.14) 4356.3,2860.24 5079.65,2860.24 5119.09,2899.68 5119.09,2906.5 5112.2,2913.39 5112.2,2921.26 5119.09,2928.15 5119.09,2953.74 C221.1@5114.17,2958.66
  Bottom w3.94: v1(3038.98,2181.89) 3044.88,2175.98 3059.06,2175.98 3080.71,2154.33 3080.71,2098.56 3090.69,2088.58 3118.11,2088.58 3125.98,2096.46 3143.56,2096.46 3177.03,2129.92 3186.87,2129.92 3551.18,2129.92 4281.5,2860.24 4344.49,2860.24 v1(4350.39,2866.14)
PCIE0_SOC_TXP: C222.1 U33.122 | length 2606.3
  Top w3.94: v1(3038.98,2160.24) 3040.94,2162.2 U33.122@3074.8,2162.2 ; v1(4350.39,2844.49) 4356.3,2850.39 5083.73,2850.39 5128.94,2895.6 5128.94,2953.74 C222.1@5133.86,2958.66
  Bottom w3.94: v1(3038.98,2160.24) 3044.88,2166.14 3054.98,2166.14 3070.87,2150.25 3070.87,2094.49 3086.61,2078.74 3122.19,2078.74 3130.06,2086.61 3147.64,2086.61 3181.1,2120.08 3555.26,2120.08 4285.57,2850.39 4344.49,2850.39 v1(4350.39,2844.49)
PCIE0_WAKEN_M0: J3.37 R297.2 | length 1552.2
  Top w3.94: J3.37@3902.76,3289.77 3902.76,3298 3902.76,3329.13 v1(3918.5,3344.88) ; v1(5218.5,2937.01) R297.2@5218.5,2958.66
  Bottom w3.94: v1(3918.5,3344.88) 3946.46,3316.93 4145.67,3316.93 4391.73,3070.87 4580.71,3070.87 4696.85,2954.72 5200.79,2954.72 v1(5218.5,2937.01)
PCIE1_CLKREQN_M0: J3.34 P15.1 | length 88.6
  Top w3.94: v1(3934.25,3118.9) 3934.25,3180.7 J3.34@3934.26,3185.83
  Bottom w3.94: v1(3934.25,3118.9) P15.1@3955.91,3118.9
PCIE1_PERSTN: J3.36 P16.1 | length 118.7
  Top w3.94: J3.36@3918.51,3185.83 3918.51,3181.3 3918.5,3111.02 v1(3934.25,3095.28)
  Bottom w3.94: P16.1@3934.25,3073.62 v1(3934.25,3095.28)
PCIE1_REFCLKN: J3.42 P13.1 | length 120.7
  Top w3.94: J3.42@3871.26,3185.83 3871.26,3180.4 3871.26,3109.06 v1(3887.01,3093.31)
  Bottom w3.94: P13.1@3887.01,3071.65 v1(3887.01,3093.31)
PCIE1_REFCLKP: J3.40 P12.1 | length 88.6
  Top w3.94: v1(3887.01,3118.9) 3887.01,3176.7 J3.40@3887.01,3185.83
  Bottom w3.94: P12.1@3865.35,3118.9 v1(3887.01,3118.9)
PCIE1_RXN/USB3_OTG1_SSRXN: D40.2 J3.60 USB1.5 | length 4722.8
  Top w3.94: USB1.5@1968.5,308.66 1968.5,357.68 1962.01,364.17 1936.02,364.17 1933.07,367.13 1933.07,406.19 1942.24,415.35 1966.54,415.35 1976.38,425.2 1976.38,435.04 D40.2@1992.13,450.79 1985.64,460.22 1976.38,469.49 1976.38,480.31 1984.25,488.19 1984.25,496.06 1976.38,503.94 1976.38,513.78 2013.78,551.18 2212.6,551.18 2326.77,665.35 2351.69,665.35 2400.9,714.57 2411.42,714.57 v1(2417.32,708.66) ; v1(3710.63,698.82) 3716.54,704.72 3716.54,735.21 3848.43,867.1 3848.43,2964.57 3733.46,3079.53 3733.46,3157.48 3729.53,3161.42 3729.53,3183.8 J3.60@3729.53,3185.83
  Bottom w3.94: v1(2417.32,708.66) 2423.23,714.57 3711.31,714.57 3716.54,709.34 3716.54,704.72 v1(3710.63,698.82)
PCIE1_RXP/USB3_OTG1_SSRXP: D36.2 J3.58 USB1.6 | length 4742.3
  Top w3.94: USB1.6@1889.76,308.66 1889.76,357.68 1896.26,364.17 1922.24,364.17 1925.2,367.13 1925.2,409.45 1938.98,423.23 1963.27,423.23 1968.5,428.46 1968.5,435.04 D36.2@1952.76,450.79 1959.24,460.22 1968.5,469.49 1968.5,517.04 2010.52,559.06 2209.34,559.06 2323.51,673.23 2348.43,673.23 2397.64,722.44 2411.42,722.44 v1(2417.32,728.35) ; v1(3730.32,698.82) 3724.41,704.72 3724.41,731.95 3856.3,863.84 3856.3,2967.83 3741.34,3082.79 3741.34,3157.48 3745.28,3161.42 3745.28,3182.7 J3.58@3745.28,3185.83
  Bottom w3.94: v1(2417.32,728.35) 2423.23,722.44 3714.57,722.44 3724.41,712.6 3724.41,704.72 v1(3730.32,698.82)
PCIE1_TXN/USB3_OTG1_SSTXN: C204.1 J3.54 | length 4819.3
  Top w3.94: C204.1@1700.79,533.46 1690.94,533.46 1685.04,539.37 1685.04,547.24 1687.01,549.21 1692.91,549.21 1694.88,551.18 1694.88,559.06 1692.91,561.02 1687.01,561.02 1685.04,562.99 1685.04,572.83 1738.03,625.83 2182.24,625.83 2310.35,753.94 2320.87,753.94 v1(2326.77,748.03) ; v1(3759.84,716.54) 3765.75,722.44 3765.75,733.24 3885.83,853.32 3885.83,2984.25 3780.71,3089.37 3780.71,3157.48 3776.77,3161.42 J3.54@3776.77,3182.2 ; J3.54@3776.78,3182.2 J3.54@3776.78,3185.83
  Bottom w3.94: v1(2326.77,748.03) 2332.68,753.94 3740.83,753.94 3765.75,729.02 3765.75,722.44 v1(3759.84,716.54)
PCIE1_TXP/USB3_OTG1_SSTXP: C205.1 J3.52 | length 4830.1
  Top w3.94: C205.1@1661.42,533.46 1671.26,533.46 1677.17,539.37 1677.17,576.1 1734.77,633.7 1736.4,633.7 1736.54,633.84 2179.29,634.01 2307.09,761.81 2320.87,761.81 v1(2326.77,767.72) ; v1(3779.53,716.54) 3773.79,722.27 3773.79,730.15 3893.7,850.06 3893.7,2987.51 3788.58,3092.63 3788.58,3157.48 3792.52,3161.42 3792.52,3181.9 J3.52@3792.52,3185.83
  Bottom w3.94: v1(2326.77,767.72) 2332.68,761.81 3744.09,761.81 3773.62,732.28 3773.62,722.44 v1(3779.53,716.54)
PDM1_CLK1_M1: J17.5 U33.96 | length 3148.9
  Top w3.94: v1(4382.28,2744.88) U33.96@4415.35,2744.88
  Bottom w3.94: J17.5@1675.59,2132.68 1743.31,2064.96 2095.53,2064.96 2156.56,2125.98 2360.24,2125.98 2480.32,2005.91 3562.68,2005.91 4293,2736.22 4373.62,2736.22 v1(4382.28,2744.88)
PDM1_SDI1_M1: J17.6 U33.94 | length 3232.9
  Top w3.94: J17.6@1675.59,2232.68 1719.29,2188.98 1799.21,2188.98 1834.65,2153.54 v1(1834.65,2096.46) ; v1(4324.8,2761.81) 4357.48,2729.13 U33.94@4415.35,2729.13
  Bottom w3.94: v1(1834.65,2096.46) 1850.39,2080.71 2084.65,2080.71 2147.64,2143.7 2372.05,2143.7 2494.09,2021.65 3549.21,2021.65 4289.37,2761.81 v1(4324.8,2761.81)
PDM1_SDI2_M1: J17.11 U33.111 | length 1388.3
  Top w3.94: J17.11@1975.59,2132.68 2025.98,2183.07 v1(2125.98,2183.07) ; U33.111@3178.74,2083.46 v1(3224.41,2083.46)
  Bottom w3.94: v1(2125.98,2183.07) 2374.02,2183.07 2511.81,2045.28 3112.2,2045.28 3135.83,2068.9 3209.84,2068.9 v1(3224.41,2083.46)
PHY1_LED0_Y1: R242.2 U33.19 | length 2877.4
  Top w3.94: R242.2@2631.89,844.49 2649.61,844.49 2683.07,877.95 3442.91,877.95 3519.68,954.72 v1(3519.68,1047.24) ; U33.19@4520.08,2146.46 4547.24,2146.46 4578.74,2114.96 4578.74,1950.79 v1(4570.87,1942.91)
  Bottom w3.94: v1(3519.68,1047.24) 3519.68,1358.27 3645.67,1484.25 3777.56,1484.25 4220.47,1927.17 4555.12,1927.17 v1(4570.87,1942.91)
PHY1_LED1_G: D16.1 R252.1 U33.17 | length 2982.5
  Top w3.94: R252.1@2484.25,891.73 2509.84,891.73 D16.1@2525.59,875.98 2547.24,897.64 3431.1,897.64 3500,966.54 3500,998.03 v1(3488.19,1009.84) ; U33.17@4520.08,2130.71 4547.24,2130.71 4568.9,2109.06 4568.9,1966.54 v1(4545.28,1942.91)
  Bottom w3.94: v1(3488.19,1009.84) 3503.94,1025.59 3503.94,1362.2 3635.83,1494.09 3773.62,1494.09 4222.44,1942.91 v1(4545.28,1942.91)
PHY1_LED2_Y: D15.1 R237.2 R241.1 U33.15 | length 2917.4
  Top w3.94: R241.1@2561.02,838.58 R237.2@2586.61,838.58 2586.61,852.36 2592.52,858.27 2629.92,858.27 2633.86,862.2 D15.1@2633.86,875.98 2661.42,875.98 2673.23,887.8 3437.01,887.8 3509.84,960.63 3509.84,1025.59 v1(3488.19,1047.24) ; U33.15@4520.08,2114.96 4547.24,2114.96 4559.06,2103.15 4559.06,1982.28 v1(4545.28,1968.5)
  Bottom w3.94: v1(3488.19,1047.24) 3488.19,1360.24 3631.89,1503.94 3769.68,1503.94 4234.25,1968.5 v1(4545.28,1968.5)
